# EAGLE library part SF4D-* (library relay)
POLARISED, MONOSTABLE RELAY WITH FORCIBLY GUIDED DOUBLE CONTACTS NAiS Source: http://www.mew-europe.com/.. en_ds_61407_0002.pdf
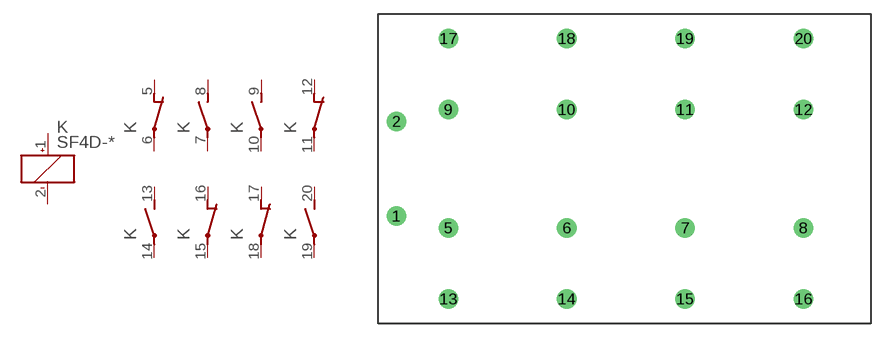
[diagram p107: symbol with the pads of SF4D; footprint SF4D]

Designator prefix K; gates 1=K+- 2=O 3=S 4=S 5=O 6=S 7=O 8=O 9=S

## SF4D-5V (OC_FARNELL: unknown; OC_NEWARK: unknown), SF4D-9V (OC_FARNELL: unknown; OC_NEWARK: unknown), SF4D-12V (OC_FARNELL: unknown; OC_NEWARK: unknown), SF4D-18V (OC_FARNELL: unknown; OC_NEWARK: unknown), SF4D-21V (OC_FARNELL: unknown; OC_NEWARK: unknown), SF4D-24V (OC_FARNELL: unknown; OC_NEWARK: unknown), SF4D-36V (OC_FARNELL: unknown; OC_NEWARK: unknown), SF4D-48V (OC_FARNELL: unknown; OC_NEWARK: unknown), SF4D-60V (OC_FARNELL: unknown; OC_NEWARK: unknown)  [SF4D]
1  1:+  pas
2  1:-  pas
5  2:O  pas
6  2:P  pas
7  3:P  pas
8  3:S  pas
9  4:S  pas
10  4:P  pas
11  5:P  pas
12  5:O  pas
13  6:S  pas
14  6:P  pas
15  7:P  pas
16  7:O  pas
17  8:O  pas
18  8:P  pas
19  9:P  pas
20  9:S  pas

## Footprint SF4D (pad centres in mm)
POLARISED, MONOSTABLE RELAY WITH FORCIBLY GUIDED DOUBLE CONTACTS NAiS Source: http://www.mew-europe.com/.. en_ds_61407_0002.pdf
drill 1.4 round: 1 -24.638,-5.08; 2 -24.638,5.08; 5 -19.05,-6.35; 6 -6.35,-6.35; 7 6.35,-6.35; 8 19.05,-6.35; 9 -19.05,6.35; 10 -6.35,6.35; 11 6.35,6.35; 12 19.05,6.35; 13 -19.05,-13.97; 14 -6.35,-13.97; 15 6.35,-13.97; 16 19.05,-13.97; 17 -19.05,13.97; 18 -6.35,13.97; 19 6.35,13.97; 20 19.05,13.97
